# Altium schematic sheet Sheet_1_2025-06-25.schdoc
size 51 x 40 mm
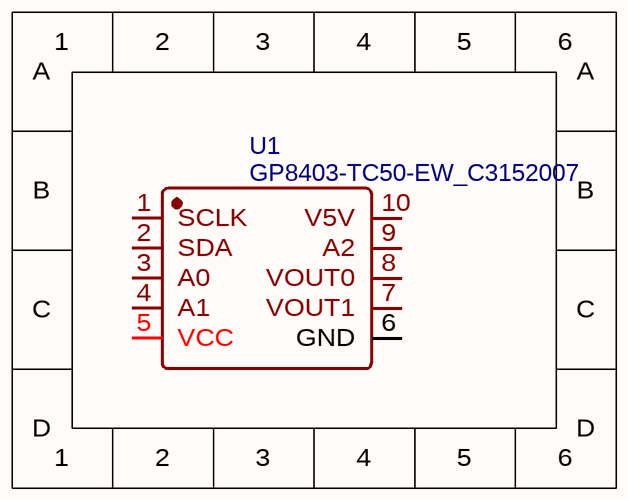
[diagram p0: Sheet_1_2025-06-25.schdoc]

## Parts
U1  GP8403-TC50-EW_C3152007  [ESSOP-10_L4.9-W3.9-P1.00-LS6.0-BL-EP]

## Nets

Not connected (* = marked no-connect by the designer): U1 1(SCLK) 2(SDA) 3(A0) 4(A1) 5(VCC) 6(GND) 7(VOUT1) 8(VOUT0) 9(A2) 10(V5V)

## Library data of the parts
U1 = GP8403-TC50-EW_C3152007: Manufacturer: Guestgood(客益); Contributor: lcsc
